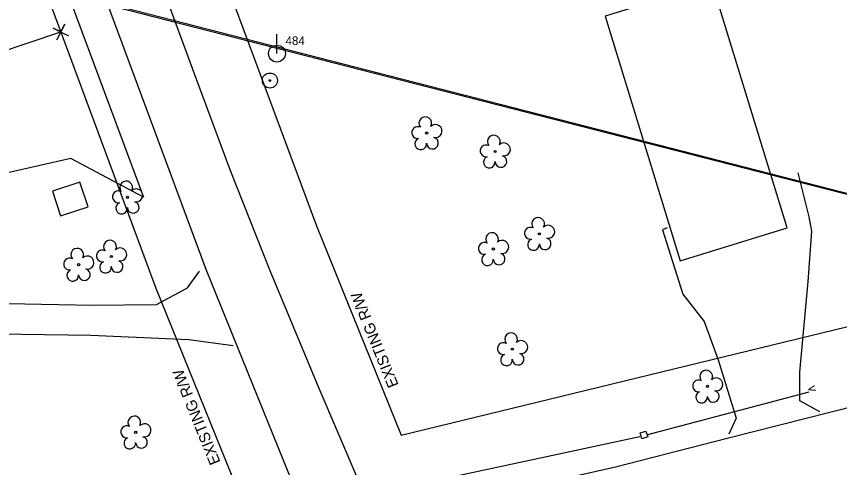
# Model space of a CAD drawing. Extents: x 1380524 to 1382335, y 594765 to 596944.
# Drawn here: x 1381752.4 to 1381991.4, y 595908.1 to 596039.1 of the extents above; entities that cross this region are included whole.
import ezdxf

# ---------------------------------------------------------------- set-up
doc = ezdxf.new("R2010")
doc.units = 0
for name, color, linetype in [('Exist Other Culture Fence Line', 7, 'Continuous'), ('Exist Right of Way Line Text', 7, 'Continuous'), ('Exist Roads EOP', 7, 'Continuous'), ('Exist Structure Major Bridge WW', 7, 'Continuous'), ('Exist Utilities Power Tower Text', 7, 'Continuous'), ('Exist Vegetation Tree CELL', 7, 'Continuous'), ('Prop Drainage Ditch Base Lines', 7, 'Continuous'), ('Prop Drainage Ditch Flow Line', 7, 'Continuous'), ('Prop Drainage Structure Box Number Symbol CELL', 7, 'Continuous'), ('Prop Drainage Structure Pipe Elbow Label', 7, 'Continuous'), ('Prop Earthen Structure Cut Ditch Special Detail CELL', 7, 'Continuous'), ('Prop Earthen Structure Cut Ditch Special Detail Label', 7, 'Continuous'), ('Prop Earthen Structure Ditch Flow Line', 7, 'Continuous'), ('Prop Erosion Rip Rap At Embankment Detail CELL', 7, 'Continuous')]:
    doc.layers.add(name, color=color, linetype=linetype)

# ---------------------------------------------------------------- blocks, each defined once
blk = doc.blocks.new('EXIST UTILITIES OTHER LOCATED OBJECT')
at = {"layer": 'Prop Earthen Structure Cut Ditch Special Detail CELL'}
for radius in [0.0436, 0.0048]:
    blk.add_circle((0, 0), radius, dxfattribs=at)
blk = doc.blocks.new('EXIST VEGETATION TREE')
at = {"layer": 'Prop Erosion Rip Rap At Embankment Detail CELL'}
blk.add_line((0, 0), (0, 0), dxfattribs=at)
blk.add_circle((0, 0), 0.00652, dxfattribs=at)
for centre, radius, start, end in [((-0.0077, 0.0575), 0.0371, 330.1651, 219.7134), ((0.051, 0.0118), 0.038, 257.1011, 134.1999), ((-0.0521, 0.0031), 0.0345, 62.6636, 279.3457), ((-0.0341, -0.0624), 0.0338, 111.5671, 6.231), ((0.0335, -0.058), 0.034, 181.2822, 74.56)]:
    blk.add_arc(centre, radius, start, end, dxfattribs=at)
blk = doc.blocks.new('EXIST UTILITIES POWER POLE')
at = {"layer": 'Exist Other Culture Fence Line'}
for q in [(0, 0.1125), (0, 0)]:
    blk.add_line((0, 0), q, dxfattribs=at)
blk.add_circle((0, 0), 0.049, dxfattribs=at)

msp = doc.modelspace()

# ---------------------------------------------------------------- linework, layer by layer
at = {"layer": 'Exist Other Culture Fence Line'}
for q in [(1381828.01, 596033.91), (1381828.01, 596028.28)]:
    msp.add_line((1381828.01, 596028.28), q, dxfattribs=at)
msp.add_circle((1381828.01, 596028.28), 2.45, dxfattribs=at)
at = {"layer": 'Exist Roads EOP'}
msp.add_line((1381864.07, 595917.48), (1382241.54, 596009.42), dxfattribs=at)
for points in [[(1381803.49, 596075.21), (1381839.46, 595978.27), (1381864.07, 595917.48)], [(1381756.61, 596057.82), (1381792.83, 595960.19), (1381822.94, 595885.83), (1381838.07, 595842.58)]]:
    msp.add_lwpolyline(points, dxfattribs=at)
at = {"layer": 'Exist Structure Major Bridge WW'}
msp.add_line((1381765.24, 596034.56), (1381765.24, 596034.56), dxfattribs=at)
msp.add_lwpolyline([(1381764.12, 596032.32), (1381766.36, 596036.79), (1381765.24, 596034.56), (1381763.01, 596035.68), (1381767.48, 596033.44)], dxfattribs=at)
at = {"layer": 'Exist Utilities Power Tower Text'}
msp.add_line((1381499.76, 595946.4), (1381765.24, 596034.56), dxfattribs=at)
at = {"layer": 'Prop Drainage Ditch Base Lines'}
for points in [[(1381923.31, 596039.17), (1381945.14, 595968.12), (1381976.25, 595977.68), (1381954.42, 596048.73)], [(1381762.81, 595988.38), (1381765.19, 595981.14), (1381773.14, 595983.74), (1381770.77, 595990.99)]]:
    msp.add_lwpolyline(points, close=True, dxfattribs=at)
at = {"layer": 'Prop Drainage Ditch Flow Line'}
msp.add_lwpolyline([(1381933.47, 595918.11), (1381935.16, 595918.66), (1381935.7, 595917), (1381934.01, 595916.45)], close=True, dxfattribs=at)
at = {"layer": 'Prop Drainage Structure Box Number Symbol CELL'}
for points in [[(1382083.99, 595964.39), (1380966.64, 596251.47), (1381106.82, 596554.99), (1381897.61, 596920.15), (1382148.43, 596473.2)], [(1382083.62, 595964.41), (1382120.69, 595773.82), (1382095.82, 595646.75), (1382010.85, 595488.75), (1381848.52, 595352.32), (1381617.36, 595239.15), (1381304.92, 595184.07), (1381005.77, 595330.75), (1380937.13, 595525.19), (1380768.47, 595849.39), (1380967, 596250.36)]]:
    msp.add_lwpolyline(points, close=True, dxfattribs=at)
at = {"layer": 'Prop Drainage Structure Pipe Elbow Label'}
for points in [[(1381935.7, 595917.71), (1381982.57, 595930.08)], [(1381862.51, 595901.85), (1381933.42, 595917.07)]]:
    msp.add_lwpolyline(points, dxfattribs=at)
at = {"layer": 'Prop Earthen Structure Cut Ditch Special Detail Label'}
msp.add_lwpolyline([(1381763.26, 596056.35), (1381789.24, 595986.58), (1381768.13, 595997.86), (1381730.48, 595989.33), (1381698.5, 596031.05), (1381723.1, 596070.54)], dxfattribs=at)
at = {"layer": 'Prop Earthen Structure Ditch Flow Line'}
for points in [[(1381771.25, 596063.05), (1381807.38, 595965.66), (1381837.55, 595891.15), (1381853.43, 595845.6)], [(1382091.45, 595950.01), (1382040.09, 595937.29), (1382004.26, 595928.01), (1381958.8, 595916.53), (1381926.33, 595908.18), (1381894.21, 595900.91), (1381876.52, 595897.14), (1381867, 595896.29), (1381860.37, 595897.28), (1381854.86, 595900.27), (1381851.95, 595903.63), (1381839.95, 595931.67), (1381826.08, 595965.16), (1381814.38, 595994.56), (1381803.44, 596023.95), (1381793.75, 596050.62), (1381789.17, 596063.13)], [(1381985.72, 595924.29), (1381979.88, 595927.46), (1381979.84, 595935.73), (1381982.3, 595962.07), (1381983.41, 595976.72), (1381982.63, 595980.88), (1381979.39, 595993.65)], [(1381941.36, 595977.65), (1381939.96, 595977.12), (1381945.95, 595958.44), (1381952.12, 595950.52), (1381956.17, 595939.34), (1381961.41, 595922.4), (1381959.26, 595917.75)], [(1381701.67, 595966.11), (1381739.83, 595955.93), (1381774.45, 595955.2), (1381793.07, 595955.39), (1381802.07, 595960.27), (1381805.56, 595965.08)], [(1381815.33, 595943.41), (1381802.45, 595945.14), (1381773.95, 595946.45), (1381733.61, 595947.02), (1381700.47, 595948.15)]]:
    msp.add_lwpolyline(points, dxfattribs=at)

# ---------------------------------------------------------------- block references
at = {"layer": 'Exist Other Culture Fence Line', "xscale": 50, "yscale": 50}
msp.add_blockref('EXIST UTILITIES POWER POLE', (1381828.01, 596028.28), dxfattribs=at)
at = {"layer": 'Prop Earthen Structure Cut Ditch Special Detail CELL', "xscale": 50, "yscale": 50}
msp.add_blockref('EXIST UTILITIES OTHER LOCATED OBJECT', (1381825.96, 596020.47), dxfattribs=at)
at = {"layer": 'Prop Erosion Rip Rap At Embankment Detail CELL', "xscale": 50, "yscale": 50}
for p in [(1381871.49, 596005.19), (1381891.39, 595999.86), (1381784.6, 595986.53), (1381904.25, 595975.95), (1381890.88, 595971.54), (1381779.92, 595969.36), (1381770.4, 595967), (1381896.4, 595942.45), (1381953.07, 595931.63), (1381786.98, 595918.29)]:
    msp.add_blockref('EXIST VEGETATION TREE', p, dxfattribs=at)

# ---------------------------------------------------------------- texts
at = {"layer": 'Exist Right of Way Line Text'}
for p in [(1381863.4, 595932.05), (1381811.66, 595909.65)]:
    msp.add_text('EXISTING R/W', height=3.2, rotation=112.0436, dxfattribs=at).set_placement(p)
at = {"layer": 'Exist Vegetation Tree CELL'}
msp.add_text('484', height=2.5, dxfattribs=at).set_placement((1381830.51, 596030.78))
msp.add_text('484', height=2.5, dxfattribs=at).set_placement((1381830.51, 596030.78))
at = {"layer": 'Prop Drainage Structure Pipe Elbow Label'}
msp.add_text('v', height=2.65, rotation=285.0237, dxfattribs=at).set_placement((1381982.18, 595931.53))

doc.saveas('drawing.dxf')
